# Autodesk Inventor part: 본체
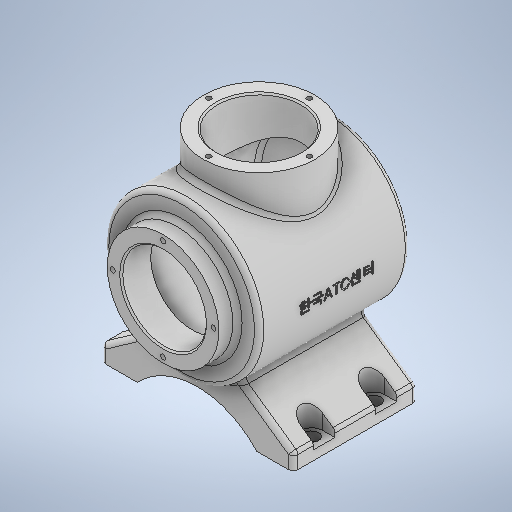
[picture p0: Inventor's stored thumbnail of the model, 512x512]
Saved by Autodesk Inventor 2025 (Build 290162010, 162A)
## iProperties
Created: 2024-07
Part Number: 본체
Material: 일반
Document SubType Name: Modeling
Designer: 계정
Density: 1 g/cm^3
Appearance: 기본값
Author: 계정
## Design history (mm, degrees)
sketch "스케치2"
  geometry: L1 (-0.621, -24.022)-(-62, -67); L2 (-62, -67)-(-62, -77); L3 (-62, -77)-(62, -77); L4 (62, -77)-(62, -67); L5 (62, -67)-(0.621, -24.022); L6 (0.621, -24.022)-(-0.621, -24.022); L7 (0, 38.547)-(0, -47.746); A1 r 52.096 centre (0, -112.096) between (38.5, -77) and (-38.5, -77); 3 further points
  constraints: 14 end point, 4 perpendicular, 3 point on circle, 3 point on line, 1 centre point, 1 midpoint, 1 vertical, 1 vertical alignment, 2 other
  dimensions: "d3" = 10 distance of L1.end L2.end; "d4" = 55 deg angle of L5 L4; "d5" = 77 distance from line of point (0, 0) L3; "d6" = 124 distance of L2.end L3.end; "d7" = 17 distance from line of L3 point (0, -60); "d8" = 77 distance of A1.start A1.end; "d104" = 10 distance of L3.end L4.end (derived)
extrude "돌출2" join sketch "스케치2" stored distance "d9" = 80; taper "d10" = 0 deg
sketch "스케치3"
  geometry: L1 (50, -46.336)-(-50, -46.336); L2 (-50, -46.336)-(-50, 50); L3 (-50, 50)-(50, 50); L4 (50, 50)-(50, -46.336); L5 (-0.621, 40)-(0.621, 40) reference; L6 (0.621, -40)-(0.621, 40) reference; L7 (-0.621, 40)-(0.621, 40) reference; L8 (-0.621, -40)-(-0.621, 40) reference; L9 (0.621, -40)-(-0.621, -40) reference; L10 (62, -40)-(62, 40) reference; L11 (-62, -40)-(-62, 40) reference; L12 (-67.633, 0)-(66.391, 0); L13 (0, -58)-(0, 121.018); A1 r 113 centre (0, 55) between (-50, -46.336) and (50, -46.336); 6 further points
  constraints: 12 end point, 3 midpoint, 3 point on circle, 2 horizontal, 2 parallel, 1 centre point, 1 perpendicular, 1 vertical
  dimensions: "d13" = 100 distance of L2.end L3.end; "d15" = 226 diameter of A1; "d16" = 108 distance from line of L3 L13.start; "d18" = 50 distance from line of point (-0.621, 0) L3; "d19" = 62 distance from line of L10 point (0, 50)
revolve "회전1" sketch "스케치3" stored, may be unused: angle "d20" = 90 deg
sketch "스케치4"
  geometry: C1 r 36 at (0, 0); 1 further point
  constraints: 1 centre point, 1 coincident
  dimensions: "d21" = 72 diameter of C1
extrude "돌출3" join sketch "스케치4" distance "d22" = 12; taper "d23" = 0 deg
sketch "스케치6"
  geometry: C1 r 36 at (0, 0); 1 further point
  constraints: 1 centre point, 1 coincident
  dimensions: "d34" = 72 diameter of C1
extrude "돌출4" join sketch "스케치6" distance "d35" = 65; taper "d36" = 0 deg
sketch "스케치5"
  geometry: L1 (0, 73.578)-(0, -117.524); L2 (36, 62)-(-36, 62) reference; L3 (0, 62)-(27, 62); L4 (27, 62)-(27, 43); L5 (27, 43)-(43, 43); L6 (43, 43)-(43, -41.887); A1 r 113 centre (0, 55) between (-50, -46.336) and (50, -46.336) reference; A2 r 106 centre (0, 55) between (0, -51) and (43, -41.887); 3 further points
  constraints: 10 end point, 3 perpendicular, 3 point on line, 2 point on circle, 1 centre point, 1 collinear, 1 horizontal, 1 midpoint, 1 vertical
  dimensions: "d24" = 19 distance of L3.end L4.end; "d25" = 86 diameter of L5.end L1; "d26" = 54 diameter of L3.end L1; "d27" = 7 radial gap between concentric circles of A1 A2
revolve "회전2" sketch "스케치5" stored, may be unused: angle "d28" = 360 deg
fillet "모깎기1" dims "d29" = 3
fillet "모깎기2" dims "d30" = 3
chamfer "모따기1" distance "d31" = 1; stored, may be unused: second distance "d32" = 2, angle "d33" = 45 deg
sketch "스케치7"
  geometry: C1 r 36 at (0, 0) reference; 2 further points
  constraints: 1 coincident
hole "구멍1" sketch "스케치7" at (0, 0) diameter "d37" = 54; stored, may be unused: countersink angle "d41" = 90 deg, drill point angle "d43" = 0 deg; dims "d38" = 8, "d39" = 4, "d40" = 2, "d42" = 45
chamfer "모따기2" distance "d44" = 1; stored, may be unused: second distance "d45" = 2, angle "d46" = 45 deg
fillet "모깎기3" dims "d47" = 3
fillet "모깎기4" dims "d48" = 3
fillet "모깎기5" dims "d49" = 3
fillet "모깎기6" dims "d50" = 3
fillet "모깎기7" dims "d51" = 3
node "작업 평면1"
sketch "스케치8"
  geometry: L1 (70, -20)-(54, -20); L2 (70, -13)-(54, -13); L3 (54, -27)-(70, -27); L4 (62, 37)-(62, -37) reference; L5 (38.5, -40)-(59, -40) reference; L6 (54, 13)-(70, 13); L7 (70, 27)-(54, 27); L8 (-70, -27)-(-54, -27); L9 (-54, -13)-(-70, -13); L10 (-70, 13)-(-54, 13); L11 (-54, 27)-(-70, 27); L12 (-62, -37)-(-62, 37) reference; L13 (-38.5, 40)-(-59, 40) reference; L14 (-59, -40)-(-38.5, -40) reference; L15 (59, 40)-(38.5, 40) reference; A1 r 7 centre (70, -20) between (70, -27) and (70, -13); A2 r 7 centre (54, -20) between (54, -13) and (54, -27); A3 r 7 centre (54, 20) between (54, 27) and (54, 13); A4 r 7 centre (70, 20) between (70, 13) and (70, 27); A5 r 7 centre (-70, -20) between (-70, -13) and (-70, -27); A6 r 7 centre (-54, -20) between (-54, -27) and (-54, -13); A7 r 7 centre (-70, 20) between (-70, 27) and (-70, 13); A8 r 7 centre (-54, 20) between (-54, 13) and (-54, 27); 8 further points
  constraints: 20 end point, 16 point on circle, 16 tangent, 8 centre point, 7 midpoint, 5 point on line, 4 parallel, 1 horizontal
  dimensions: "d53" = 8 distance from line of L4 L1.end; "d54" = 20 distance between parallel lines of L5 L1; "d55" = 14 distance of point (62, -13) point (62, -27); "d56" = 8 distance from line of L4 A3.centre; "d57" = 8 distance from line of L12 A6.centre; "d58" = 8 distance from line of L12 A8.centre; "d59" = 20 distance from line of A8.centre L13; "d60" = 20 distance from line of A6.centre L14; "d61" = 14 distance between parallel lines of L9 L8; "d62" = 14 distance between parallel lines of L11 L10; "d63" = 20 distance from line of A4.centre L15; "d64" = 14 distance between parallel lines of L6 L7; "d65" = 108 distance of A6.centre L1.end (derived); "d66" = 40 distance of A3.centre L1.end; "d67" = 40 distance of A7.centre A5.centre
extrude "돌출5" cut sketch "스케치8" distance "d68" = 20; taper "d69" = 0 deg
sketch "스케치9"
  geometry: A1 r 7 centre (-54, 20) between (-54, 13) and (-54, 27) reference; A2 r 7 centre (-54, -20) between (-54, -27) and (-54, -13) reference; A3 r 7 centre (54, -20) between (54, -13) and (54, -27) reference; A4 r 7 centre (54, 20) between (54, 27) and (54, 13) reference; 5 further points
  constraints: 4 coincident
hole "구멍2" sketch "스케치9" at (-54, 20), (-54, -20), (54, 20), (54, -20) diameter "d70" = 9; stored, may be unused: countersink angle "d74" = 90 deg, drill point angle "d76" = 0 deg; dims "d71" = 6, "d72" = 4, "d73" = 2, "d75" = 45
fillet "모깎기8" dims "d77" = 3
sketch "스케치10"
  geometry: 2 further points
  constraints: 1 horizontal alignment
  dimensions: "d85" = 32.5 distance of point (-32.5, 0) point (0, 0)
hole "구멍3" sketch "스케치10" at (-32.5, 0) diameter "d78" = 3.242; stored, may be unused: countersink angle "d82" = 90 deg, drill point angle "d84" = 120 deg; dims "d79" = 8, "d80" = 4, "d81" = 2, "d83" = 10
sketch "스케치11"
  geometry: 2 further points
  constraints: 1 vertical alignment
  dimensions: "d96" = 32.5 distance of point (0, 32.5) point (0, 0)
hole "구멍4" sketch "스케치11" at (0, 32.5) diameter "d89" = 3.242; stored, may be unused: countersink angle "d93" = 90 deg, drill point angle "d95" = 120 deg; dims "d90" = 8, "d91" = 4, "d92" = 2, "d94" = 10
node "작업 평면2"
sketch "스케치12"
  geometry: L1 (36, 62)-(-36, 62) reference; 3 further points
  constraints: 1 coincident, 1 midpoint, 1 vertical alignment, 1 other
  dimensions: "d101" = 62 distance from line of L1 point (0, 0)
feature "엠보싱1" sketch "스케치12" dims "d3" = 10, "d4" = 55 deg, "d5" = 77, "d6" = 124, "d7" = 17, "d8" = 77, "d102" = 0.5, "d103" = 0, "d104" = 10 (derived)
node "솔리드1"
pattern_circular "원형 패턴1" dims angle "d87" = 360 deg
pattern_circular "원형 패턴2" dims angle "d98" = 360 deg
node "투영된 루프1"
feature "A9D066F2-1C7D-4E18-AEED-F7BC21143FA4" dims "d37" = 54, "d38" = 8, "d39" = 4, "d40" = 2, "d41" = 90 deg, "d42" = 45, "d43" = 0
other parameters: "d52" = -71, "d100" = 174
